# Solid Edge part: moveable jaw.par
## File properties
Title: Moveable Jaw
Author: Robert a Rhodes jr
Template: Normal.par
Last saved by: Cadcim
Revision: 11
Application: Solid Edge
Material: iron
Accuracy: 0.99
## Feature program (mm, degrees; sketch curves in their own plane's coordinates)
sketch for "unnamed Protrusion 1" plane through (0, 0, 0) normal (0, -1, 0) x-axis (1, 0, 0)
  line (-36.5256, 25.2528) -> (-36.5256, -34.7472)
  line (-36.5256, -34.7472) -> (-33.0256, -34.7472)
  line (-33.0256, -34.7472) -> (-33.0256, -32.2472)
  line (-33.0256, -32.2472) -> (-30.5256, -32.2472)
  line (-30.5256, -32.2472) -> (-30.5256, -29.7472)
  line (-30.5256, -29.7472) -> (-28.0256, -29.7472)
  line (-28.0256, -29.7472) -> (-28.0256, -27.2472)
  line (-28.0256, -27.2472) -> (-25.5256, -27.2472)
  line (-25.5256, -27.2472) -> (-25.5256, -24.7472)
  line (-25.5256, -24.7472) -> (-23.0256, -24.7472)
  line (-23.0256, -24.7472) -> (-23.0256, -22.2472)
  line (-23.0256, -22.2472) -> (-20.5256, -22.2472)
  line (-20.5256, -22.2472) -> (-20.5256, -19.7472)
  line (-20.5256, -19.7472) -> (-18.0256, -19.7472)
  line (-18.0256, -22.2472) -> (-18.0256, -19.7472)
  line (-15.5256, -22.2472) -> (-18.0256, -22.2472)
  line (-15.5256, -24.7472) -> (-15.5256, -22.2472)
  line (-13.0256, -24.7472) -> (-15.5256, -24.7472)
  line (-13.0256, -27.2472) -> (-13.0256, -24.7472)
  line (-10.5256, -27.2472) -> (-13.0256, -27.2472)
  line (-10.5256, -29.7472) -> (-10.5256, -27.2472)
  line (-8.0256, -29.7472) -> (-10.5256, -29.7472)
  line (-8.0256, -32.2472) -> (-8.0256, -29.7472)
  line (-5.5256, -32.2472) -> (-8.0256, -32.2472)
  line (-5.5256, -34.7472) -> (-5.5256, -32.2472)
  line (-2.0256, -34.7472) -> (-5.5256, -34.7472)
  line (-2.0256, -34.7472) -> (-2.0256, 25.2528)
  line (-2.0256, 25.2528) -> (-36.5256, 25.2528)
extrude "unnamed Protrusion 1" add finite 18 along -normal
sketch for "Hole_1" plane through (-19.2756, 9, 25.2528) normal (0, 0, 1) x-axis (1, 0, 0)
  hole centre (0, 0) bore radius 6
hole "Hole_1" diameter 12 finite  VBottomAngle = 118 deg
sketch for "Hole_2" plane through (-2.0256, 9, -4.7472) normal (1, 0, 0) x-axis (0, 1, 0)
  hole centre (0, 23) bore radius 4.5
hole "Hole_2" diameter 9 through
chamfer "Chamfer_1" setback 2
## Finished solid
Body 1: solid body, 38 faces, 98 edges, 60 vertices.
  Faces by surface: plane 34, cylinder 3, cone 1
  Edges by curve: line 92, circle 4, intersection 2
Bounding box of the edges (mm): 34.500 x 18.000 x 60.000, from (-36.5256, 0, -34.7472) to (-2.0256, 18, 25.2528).
Cylindrical faces by radius (mm): R4.5 x2, R6 x1
Conical faces (half-angle, radius in mm at the cone's reference point): 59 deg R6 x1
Planar faces by outward normal: +x 7, +y 1, +z 1, -x 7, -y 1, -z 13, oblique 4
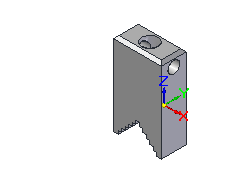
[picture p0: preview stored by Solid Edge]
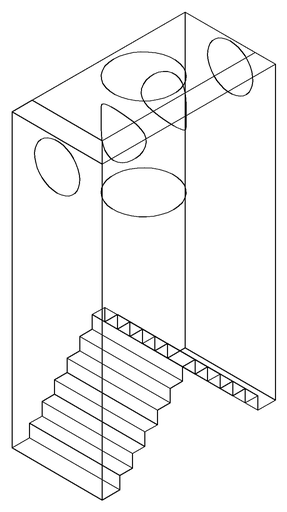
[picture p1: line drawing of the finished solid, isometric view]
